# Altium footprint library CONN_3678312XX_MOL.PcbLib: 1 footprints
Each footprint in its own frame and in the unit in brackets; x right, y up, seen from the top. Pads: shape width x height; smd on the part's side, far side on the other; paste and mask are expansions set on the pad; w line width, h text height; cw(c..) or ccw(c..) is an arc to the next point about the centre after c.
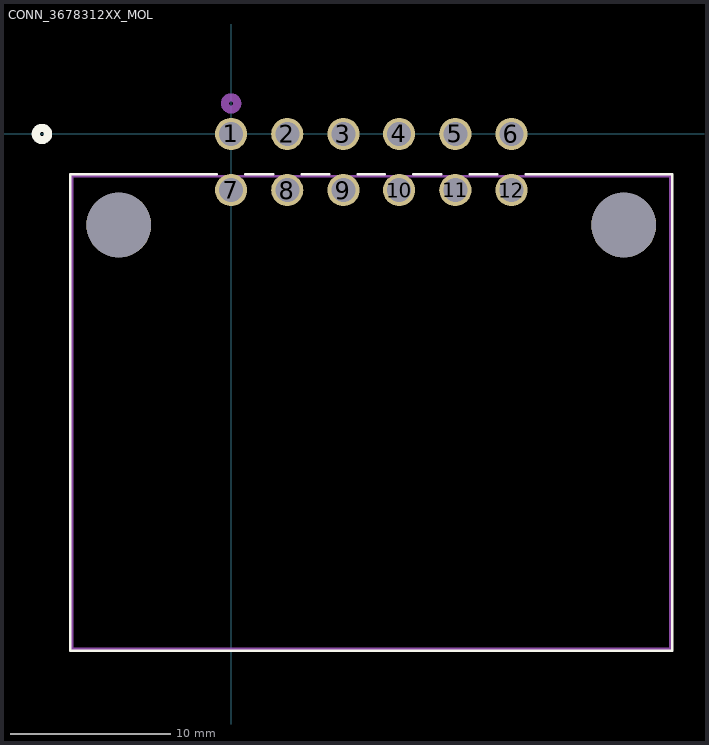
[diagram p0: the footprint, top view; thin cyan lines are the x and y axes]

## CONN_3678312XX_MOL [mil]
pads (14):
  round 79 hole 59: 1(0,0) 2(138,0) 3(276,0) 4(413,0) 5(551,0) 6(689,0) 7(0,-138) 8(138,-138) 9(276,-138) 10(413,-138) 11(551,-138) 12(689,-138)
  round 159 hole 159 unplated: ""(-276,-224) ""(965,-224)
Top Overlay:
  lines w6: -35,-99 -395,-99 -395,-1270 1084,-1270 1084,-99 724,-99 ; 35,-99 103,-99 ; 173,-99 241,-99 ; 311,-99 378,-99 ; 448,-99 516,-99 ; 586,-99 654,-99
  lines w20: -480,0 ccw(c-465,0) -450,0 ccw(c-465,0) -480,0
Bottom Overlay:
  lines w20: -480,0 ccw(c-465,0) -450,0 ccw(c-465,0) -480,0
Assembly Top:
  lines w6: -390,-1265 1079,-1265 1079,-104 -390,-104 -390,-1265
  lines w20: -15,75 ccw(c0,75) 15,75 ccw(c0,75) -15,75
3D body "367831201.stp": height 977.3, standoff -110.38, extent -382.02,-1257.14 1088.76,20.72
